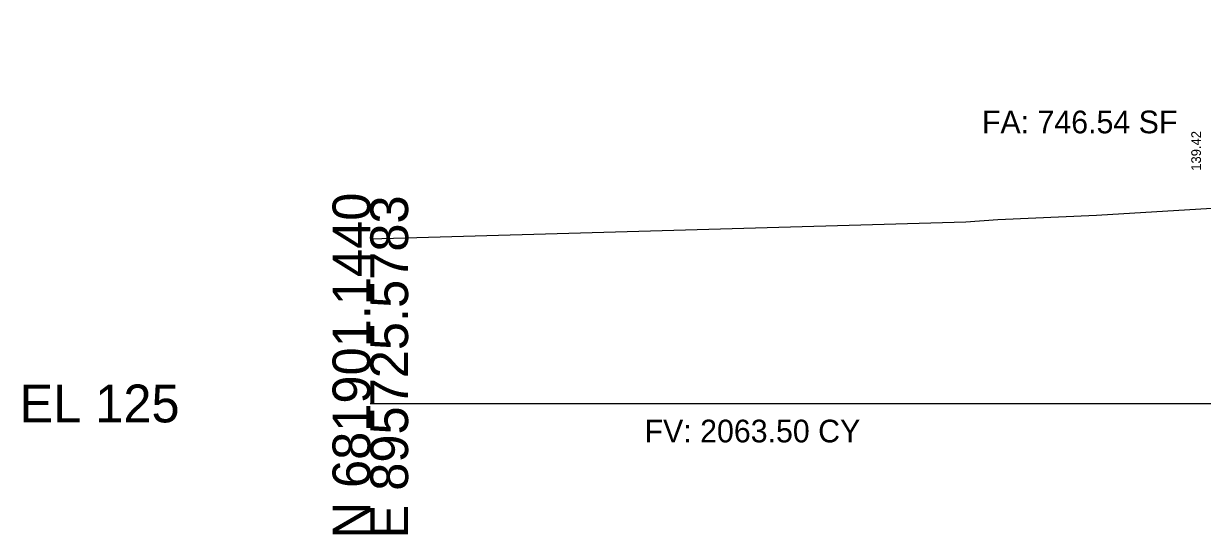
# Model space of a CAD drawing. Extents: x -100 to 7529, y -13 to 10775.
# Drawn here: x 2974.3 to 3061.7, y 5490.3 to 5528.1 of the extents above; entities that cross this region are included whole.
import ezdxf

# ---------------------------------------------------------------- set-up
doc = ezdxf.new("R2010")
doc.units = 0
for name, color, linetype in [('Draft_XS_Grid', 7, 'Continuous'), ('DTM_X_GROUND', 7, 'Continuous'), ('XS_CELL', 7, 'Continuous'), ('XS_P_TX_CLEARZONE', 7, 'Continuous'), ('XS_SHEET_EW_TX_AREA', 7, 'Continuous'), ('XS_SHEET_EW_TX_VOLUME', 7, 'Continuous')]:
    doc.layers.add(name, color=color, linetype=linetype)

msp = doc.modelspace()

# ---------------------------------------------------------------- linework, layer by layer
at = {"layer": 'DTM_X_GROUND'}
msp.add_lwpolyline([(3000, 5512.2), (3044.132, 5513.453), (3046.486, 5513.62), (3053.808, 5513.95), (3070.909, 5514.966), (3077.153, 5518.209), (3097.118, 5527.209), (3098.789, 5527.5), (3101.713, 5527.882), (3110.312, 5528.066), (3113.777, 5528.123), (3116.864, 5528.039), (3124.572, 5527.826)], dxfattribs=at)
at = {"layer": 'XS_CELL'}
msp.add_line((3000, 5500), (3150, 5500), dxfattribs=at)
msp.add_line((3000, 5500), (3150, 5500), dxfattribs=at)

# ---------------------------------------------------------------- texts
at = {"layer": 'Draft_XS_Grid'}
msp.add_text('-', height=0.0001, dxfattribs=at).set_placement((3000, 5500))
at = {"layer": 'XS_CELL'}
for s, p in [('N 681901.1440', (3000, 5490)), ('N 681901.1440', (3000, 5490)), ('E 895725.5783', (3002.8, 5490)), ('E 895725.5783', (3002.8, 5490))]:
    msp.add_text(s, height=2.8, rotation=90, dxfattribs=at).set_placement(p)
msp.add_text('EL 125', height=2.8, dxfattribs=at).set_placement((2974, 5498.6))
msp.add_text('EL 125', height=2.8, dxfattribs=at).set_placement((2974, 5498.6))
at = {"layer": 'XS_P_TX_CLEARZONE'}
msp.add_text('139.42', height=0.72, rotation=90, dxfattribs=at).set_placement((3061.549, 5517.228))
msp.add_text('139.42', height=0.72, rotation=90, dxfattribs=at).set_placement((3061.549, 5517.228))
at = {"layer": 'XS_SHEET_EW_TX_AREA'}
msp.add_text('FA: 746.54 SF', height=1.68, dxfattribs=at).set_placement((3045.318, 5520))
msp.add_text('FA: 746.54 SF', height=1.68, dxfattribs=at).set_placement((3045.318, 5520))
at = {"layer": 'XS_SHEET_EW_TX_VOLUME'}
msp.add_text('FV: 2063.50 CY', height=1.68, dxfattribs=at).set_placement((3020.319, 5497.12))
msp.add_text('FV: 2063.50 CY', height=1.68, dxfattribs=at).set_placement((3020.319, 5497.12))

doc.saveas('drawing.dxf')
